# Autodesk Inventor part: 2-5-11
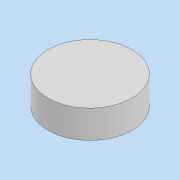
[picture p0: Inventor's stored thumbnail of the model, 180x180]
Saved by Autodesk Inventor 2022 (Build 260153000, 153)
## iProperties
Created: 2021-07
Part Number: 2-5-11
Material: 一般
Document SubType Name: Modeling
Designer: DesignLab
Density: 1 g/cm^3
Appearance: 既定
Author: DesignLab
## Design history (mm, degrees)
sketch "スケッチ1"
  geometry: C1 r 15 at (0, 0); 1 further point
  constraints: 1 centre point, 1 coincident
  dimensions: "d0" = 30 diameter of C1
extrude "押し出し1" new body sketch "スケッチ1" distance "d1" = 10; taper "d2" = 0 deg
node "ソリッド1"
